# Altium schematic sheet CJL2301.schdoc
size 127 x 101 mm
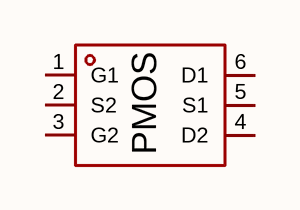
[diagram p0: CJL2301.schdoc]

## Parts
Q?  cjl2301  [SOT-23-6_L2.9-W1.6-P0.95-LS2.8-BL]  (value not drawn)

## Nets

Not connected (* = marked no-connect by the designer): Q? 1(G1) 2(S2) 3(G2) 4(D2) 5(S1) 6(D1)

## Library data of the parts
Q? = cjl2301: 数量:2个P沟道;漏源电压(Vdss):20V;连续漏极电流(Id):2.3A;导通电阻(RDS(on)):90mΩ@4.5V;耗散功率(Pd):350mW;阈值电压(Vgs(th)):400mV;; Manufacturer: CJ(江苏长电/长晶); AddInBom: yes; ModelId: 18da8f6c14a34920b3e136b5c401a119; ModelName: SOT-23-6_L2.9-W1.6-H1.5-LS2.8-P0.95; ModelTransform: 110.236,113.364,0,90,0,0,0.0005,0.0005,0; Number: 2个P沟道; Drain to Source Voltage: 20V; Current - Continuous Drain(Id): 2.3A; Pd - Power Dissipation: 350mW; Gate Threshold Voltage (Vgs(th)): 400mV; Gate Charge(Qg): 5.5nC@4.5V; Input Capacitance(Ciss): 405pF; Reverse Transfer Capacitance (Crss@Vds): 55pF; Type: P沟道; Output Capacitance(Coss): 75pF; Vgs: ±8V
